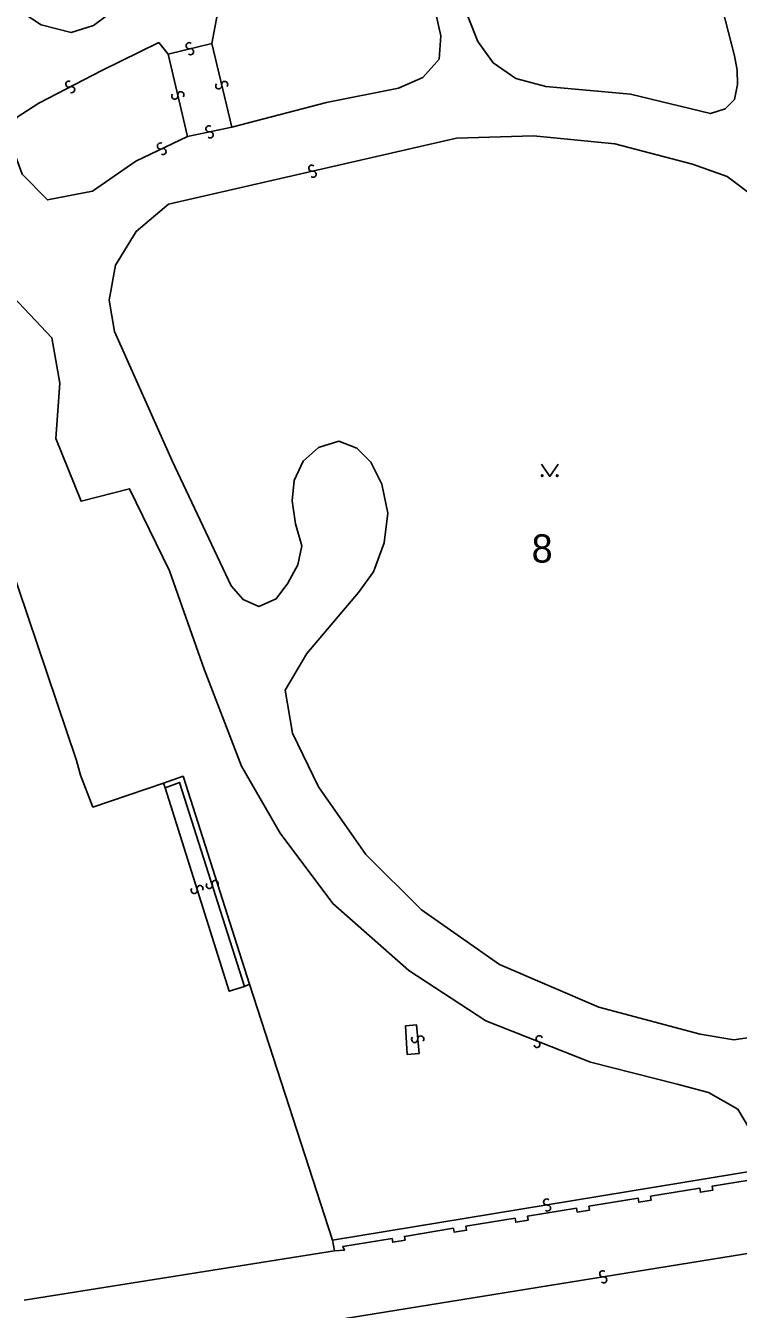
# Model space of a CAD drawing. Extents: x -600309 to -598967, y -1161267 to -1160292.
# Drawn here: x -599299.8 to -599256.9, y -1161127.6 to -1161050.3 of the extents above; entities that cross this region are included whole.
import ezdxf

# ---------------------------------------------------------------- set-up
doc = ezdxf.new("R2010")
doc.units = 0
for name, color, linetype in [('Level 1', 7, 'Continuous'), ('Level 13', 7, 'Continuous'), ('Level 3', 7, 'Continuous'), ('Level 4', 7, 'Continuous'), ('Level 5', 7, 'Continuous'), ('Level 60', 7, 'Continuous')]:
    doc.layers.add(name, color=color, linetype=linetype)

msp = doc.modelspace()

# ---------------------------------------------------------------- linework, layer by layer
at = {"layer": 'Level 1'}
for points in [[(-599291.52, -1161095.9), (-599295.76, -1161097.35), (-599296.5, -1161095.43), (-599296.75, -1161094.55), (-599302.02, -1161078.97)], [(-599286.34, -1161107.99), (-599290.33, -1161095.49), (-599291.52, -1161095.9)], [(-599281.35, -1161123.4), (-599286.34, -1161107.99)], [(-599255.55, -1161119.67), (-599258.51, -1161120.15), (-599258.47, -1161120.39), (-599259.22, -1161120.51), (-599259.25, -1161120.27), (-599262.21, -1161120.75), (-599262.18, -1161120.99), (-599262.92, -1161121.11), (-599262.95, -1161120.87), (-599265.92, -1161121.36), (-599265.88, -1161121.59), (-599266.62, -1161121.71), (-599266.66, -1161121.48), (-599269.62, -1161121.96), (-599269.58, -1161122.2), (-599270.32, -1161122.32), (-599270.36, -1161122.08), (-599273.32, -1161122.56), (-599273.28, -1161122.8), (-599274.02, -1161122.92), (-599274.06, -1161122.68), (-599277.02, -1161123.17), (-599276.98, -1161123.4), (-599277.72, -1161123.52), (-599277.76, -1161123.29), (-599280.72, -1161123.77), (-599280.63, -1161124), (-599281.22, -1161124.03)], [(-599281.22, -1161124.03), (-599299.89, -1161127.01)], [(-599281.22, -1161124.03), (-599281.35, -1161123.4)]]:
    msp.add_lwpolyline(points, dxfattribs=at)
at = {"layer": 'Level 13'}
for centre, start, end in [((-599289.973, -1161051.551), 51.25509, 283.35309), ((-599289.887, -1161051.909), 231.04064, 103.63064), ((-599297.203, -1161053.865), 64.78031, 296.87831), ((-599288.19, -1161053.961), 140.79089, 12.88889), ((-599287.831, -1161053.878), 320.57644, 193.16644), ((-599297.036, -1161054.194), 244.56585, 117.15585), ((-599290.829, -1161054.582), 140.56642, 13.15642), ((-599290.47, -1161054.499), 320.78088, 192.87888), ((-599288.778, -1161056.55), 49.29733, 281.88733), ((-599288.703, -1161056.911), 229.51178, 101.60978), ((-599291.699, -1161057.584), 62.75734, 295.34734), ((-599291.542, -1161057.917), 242.9718, 115.0698), ((-599282.59, -1161058.92), 50.28276, 282.38076), ((-599282.51, -1161059.28), 230.06831, 102.65831), ((-599289.666, -1161102.354), 144.63226, 17.22226), ((-599289.314, -1161102.246), 324.84672, 196.94472), ((-599288.756, -1161102.055), 144.81996, 17.40996), ((-599288.404, -1161101.946), 325.03441, 197.13241), ((-599276.403, -1161111.325), 132.14239, 4.73239), ((-599276.036, -1161111.296), 312.35685, 184.45484), ((-599269.048, -1161111.621), 195.67116, 68.26116), ((-599268.911, -1161111.279), 15.88561, 247.98361), ((-599268.468, -1161121.098), 46.71987, 278.81786), ((-599268.411, -1161121.462), 226.50541, 99.09541), ((-599265.088, -1161125.418), 46.54885, 278.64684), ((-599265.031, -1161125.782), 226.33439, 98.92439)]:
    msp.add_arc(centre, 0.184, start, end, dxfattribs=at)
at = {"layer": 'Level 3'}
for points in [[(-599280.58, -1161027.07), (-599273.19, -1161049.84), (-599272.6, -1161051.3), (-599271.68, -1161052.58), (-599270.31, -1161053.52), (-599268.52, -1161054.01), (-599263.43, -1161054.47), (-599258.61, -1161055.63), (-599257.73, -1161055.34), (-599257.17, -1161054.78), (-599256.98, -1161053.88), (-599257.01, -1161053.03), (-599257.17, -1161052.16), (-599260.27, -1161040.05)], [(-599281.98, -1161029.08), (-599281.77, -1161029.03), (-599275.15, -1161049.53), (-599274.84, -1161050.95), (-599274.94, -1161052.35), (-599275.91, -1161053.47), (-599277.38, -1161054.11), (-599281.7, -1161054.97), (-599287.41, -1161056.44)], [(-599288.61, -1161051.41), (-599288.2, -1161049.29), (-599287.3, -1161047.4), (-599290.12, -1161042.37), (-599291.59, -1161037.26), (-599291.23, -1161034.06), (-599288.46, -1161031.4), (-599285.95, -1161030.29)], [(-599297.91, -1161038.89), (-599296.98, -1161038.13), (-599295.77, -1161037.8), (-599294.67, -1161038.29), (-599293.86, -1161039.29), (-599292.92, -1161041.28), (-599292.51, -1161043.33), (-599292.31, -1161045.07), (-599292.49, -1161046.9), (-599293.33, -1161048.27), (-599294.4, -1161049.36), (-599295.73, -1161050.33), (-599297.06, -1161050.75), (-599298.87, -1161050.3), (-599300.37, -1161049.31), (-599301.25, -1161047.86), (-599301.42, -1161046.43), (-599301.17, -1161044.89), (-599300.55, -1161043.46), (-599297.91, -1161038.89)], [(-599300.01, -1161059.28), (-599300.91, -1161056.82), (-599300.31, -1161055.84), (-599299.01, -1161055.01), (-599295.23, -1161053.05), (-599291.8, -1161051.36), (-599291.24, -1161052.06)], [(-599291.24, -1161052.06), (-599288.61, -1161051.41)], [(-599287.41, -1161056.44), (-599288.61, -1161051.41)], [(-599291.24, -1161052.06), (-599290.06, -1161057.01)], [(-599287.41, -1161056.44), (-599290.06, -1161057.01)], [(-599290.06, -1161057.01), (-599293.17, -1161058.5), (-599295.79, -1161060.3), (-599298.49, -1161060.83), (-599300.01, -1161059.28)], [(-599287.44, -1161084.04), (-599291, -1161076.51), (-599294.45, -1161068.74), (-599294.79, -1161066.86), (-599294.4, -1161064.75), (-599293.15, -1161062.72), (-599291.21, -1161061.09), (-599273.89, -1161057.12), (-599269.26, -1161056.97), (-599264.37, -1161057.45), (-599259.7, -1161058.68), (-599257.6, -1161059.41), (-599255.82, -1161060.77)], [(-599305.26, -1161061.09), (-599303.66, -1161066.4), (-599300.56, -1161066.66), (-599298.23, -1161069.13), (-599297.74, -1161071.84), (-599297.98, -1161075.18), (-599296.47, -1161078.95), (-599293.55, -1161078.2), (-599291.15, -1161083.13), (-599289.06, -1161089.06), (-599286.82, -1161094.89), (-599284.5, -1161098.92), (-599281.33, -1161103.14), (-599276.76, -1161107.17), (-599272.13, -1161110.21), (-599265.83, -1161112.69), (-599260.62, -1161114.01), (-599258.72, -1161114.52), (-599256.97, -1161115.52), (-599256, -1161117.13), (-599255.46, -1161118.73)], [(-599254.9, -1161111.01), (-599257.21, -1161111.34), (-599259.24, -1161111.01), (-599265.33, -1161109.39), (-599271.31, -1161106.81), (-599275.99, -1161103.53), (-599279.34, -1161100.19), (-599282.19, -1161096.12), (-599283.76, -1161092.89), (-599284.2, -1161090.31), (-599282.9, -1161088.11), (-599279.78, -1161084.43), (-599278.89, -1161083.19), (-599278.23, -1161081.46), (-599278.01, -1161079.67), (-599278.37, -1161077.92), (-599279.05, -1161076.6), (-599279.88, -1161075.75), (-599280.96, -1161075.34), (-599282.18, -1161075.72), (-599283.11, -1161076.54), (-599283.66, -1161077.7), (-599283.77, -1161078.92), (-599283.58, -1161080.3), (-599283.19, -1161081.64), (-599283.44, -1161082.77), (-599284.03, -1161083.88), (-599284.73, -1161084.82), (-599285.77, -1161085.28), (-599286.73, -1161084.85), (-599287.44, -1161084.04)], [(-599360.41, -1161090.46), (-599362.08, -1161091.01), (-599359.49, -1161103.92), (-599361.4, -1161105.16), (-599355.79, -1161110.77), (-599344.03, -1161124.02), (-599341.28, -1161127.02), (-599337.28, -1161130.68), (-599333.41, -1161132.87), (-599328.69, -1161134.32), (-599323.7, -1161134.67), (-599306.03, -1161132.21), (-599289.27, -1161129.51), (-599240.86, -1161121.69)], [(-599291.52, -1161095.9), (-599291.41, -1161096.19)], [(-599291.41, -1161096.19), (-599290.54, -1161095.86), (-599286.63, -1161108.14)], [(-599291.41, -1161096.19), (-599287.56, -1161108.42), (-599286.63, -1161108.14)], [(-599286.63, -1161108.14), (-599286.34, -1161107.99)], [(-599276.96, -1161110.5), (-599276.29, -1161110.45), (-599276.14, -1161112.17), (-599276.85, -1161112.22), (-599276.96, -1161110.5)], [(-599281.35, -1161123.4), (-599255.53, -1161119.15), (-599255.46, -1161118.73)]]:
    msp.add_lwpolyline(points, dxfattribs=at)
at = {"layer": 'Level 5'}
msp.add_lwpolyline([(-599268.781, -1161076.71), (-599268.28, -1161077.46), (-599267.78, -1161076.71)], dxfattribs=at)
for centre in [(-599268.73, -1161077.41), (-599267.831, -1161077.41)]:
    msp.add_circle(centre, 0.05, dxfattribs=at)
at = {"layer": 'Level 60'}
for points in [[(-599302.02, -1161078.97), (-599296.75, -1161094.55), (-599296.5, -1161095.43), (-599295.76, -1161097.35), (-599291.52, -1161095.9), (-599290.33, -1161095.49), (-599286.34, -1161107.99), (-599281.35, -1161123.4), (-599281.22, -1161124.03), (-599299.89, -1161127.01)], [(-599290.33, -1161095.49), (-599291.52, -1161095.9), (-599295.76, -1161097.35), (-599296.5, -1161095.43), (-599296.75, -1161094.55), (-599302.02, -1161078.97)], [(-599255.55, -1161119.67), (-599258.51, -1161120.15), (-599258.47, -1161120.39), (-599259.22, -1161120.51), (-599259.25, -1161120.27), (-599262.21, -1161120.75), (-599262.18, -1161120.99), (-599262.92, -1161121.11), (-599262.95, -1161120.87), (-599265.92, -1161121.36), (-599265.88, -1161121.59), (-599266.62, -1161121.71), (-599266.66, -1161121.48), (-599269.62, -1161121.96), (-599269.58, -1161122.2), (-599270.32, -1161122.32), (-599270.36, -1161122.08), (-599273.32, -1161122.56), (-599273.28, -1161122.8), (-599274.02, -1161122.92), (-599274.06, -1161122.68), (-599277.02, -1161123.17), (-599276.98, -1161123.4), (-599277.72, -1161123.52), (-599277.76, -1161123.29), (-599280.72, -1161123.77), (-599280.63, -1161124), (-599281.22, -1161124.03), (-599281.35, -1161123.4), (-599286.34, -1161107.99), (-599290.33, -1161095.49)], [(-599299.89, -1161127.01), (-599281.22, -1161124.03), (-599280.63, -1161124), (-599280.72, -1161123.77), (-599277.76, -1161123.29), (-599277.72, -1161123.52), (-599276.98, -1161123.4), (-599277.02, -1161123.17), (-599274.06, -1161122.68), (-599274.02, -1161122.92), (-599273.28, -1161122.8), (-599273.32, -1161122.56), (-599270.36, -1161122.08), (-599270.32, -1161122.32), (-599269.58, -1161122.2), (-599269.62, -1161121.96), (-599266.66, -1161121.48), (-599266.62, -1161121.71), (-599265.88, -1161121.59), (-599265.92, -1161121.36), (-599262.95, -1161120.87), (-599262.92, -1161121.11), (-599262.18, -1161120.99), (-599262.21, -1161120.75), (-599259.25, -1161120.27), (-599259.22, -1161120.51), (-599258.47, -1161120.39), (-599258.51, -1161120.15), (-599255.55, -1161119.67)]]:
    msp.add_lwpolyline(points, dxfattribs=at)

# ---------------------------------------------------------------- texts
at = {"layer": 'Level 4'}
msp.add_text('8', height=1.7, dxfattribs=at).set_placement((-599269.37, -1161082.64))

doc.saveas('drawing.dxf')
